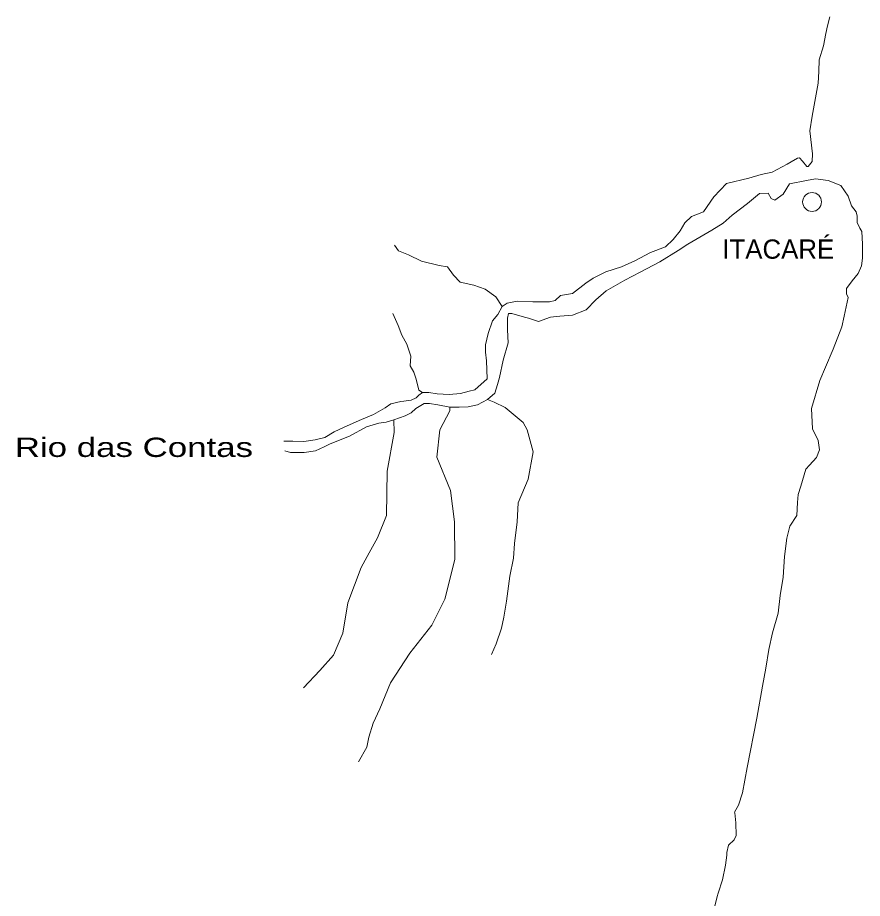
# Model space of a CAD drawing. Extents: x 47169 to 972804, y 7447977 to 9608469.
# Drawn here: x 473189 to 502148, y 8397660 to 8427856 of the extents above; entities that cross this region are included whole.
import ezdxf

# ---------------------------------------------------------------- set-up
doc = ezdxf.new("R2010")
doc.units = 0
doc.header["$LTSCALE"] = 270
doc.layers.add('1', color=7, linetype='Continuous', lineweight=13)
doc.layers.add('2', color=7, linetype='Continuous', lineweight=13)
doc.layers.add('3', color=7, linetype='Continuous')

msp = doc.modelspace()

# ---------------------------------------------------------------- linework, layer by layer
at = {"layer": '1'}
for points in [[(482317.8, 8413333.4), (482619.7, 8413333.6), (482997.1, 8413322.8), (483385.3, 8413378.3), (483719.5, 8413456), (484042.9, 8413655.3), (484387.8, 8413810.3), (484980.7, 8414076.1), (485390.4, 8414253.3), (485789.3, 8414474.8), (485983.3, 8414618.7), (486328.3, 8414696.3), (486425.4, 8414707.4), (486684.2, 8414740.7), (486856.6, 8414818.2), (486942.9, 8414906.8), (487072.2, 8415006.3), (487136.9, 8415006.4), (487287.9, 8415006.5), (487568.3, 8414962.4), (487978.1, 8414940.4), (488366.3, 8414973.8), (488668.2, 8415051.4), (488862.3, 8415095.7), (489282.7, 8415471.9), (489260.8, 8416091.3), (489228.3, 8416389.9), (489228.2, 8416633.2), (489314.4, 8417031.4), (489465.2, 8417462.8), (489648.4, 8417673), (489799.3, 8417949.6), (489971.8, 8418071.3), (490316.9, 8418137.8), (490845.4, 8418115.9), (491190.5, 8418116), (491417, 8418116.1), (491611.1, 8418160.4), (491794.4, 8418326.3), (492215, 8418392.8), (492667.8, 8418746.9), (492915.8, 8418923.9), (493358, 8419145.2), (493886.4, 8419311.3), (494350.2, 8419521.5), (494889.4, 8419798.1), (495396.3, 8419997.3), (495665.9, 8420251.7), (495903.1, 8420550.4), (496064.9, 8420815.9), (496291.3, 8421037.1), (496701.2, 8421192), (497057.1, 8421711.9), (497488.5, 8422165.4), (498254.3, 8422353.4), (498675, 8422475.1), (499052.5, 8422552.6), (499570.3, 8422829.1), (499710.5, 8422906.5), (499926.3, 8423039.2), (499991, 8423050.3), (500098.9, 8422939.7), (500239.1, 8422751.7), (500293, 8422751.7), (500422.5, 8422917.6), (500433.3, 8423183), (500347, 8423979.3), (500422.5, 8424477), (500498, 8424853), (500627.5, 8425605.1), (500659.9, 8426014.3), (500670.7, 8426412.5), (500811, 8426888.1), (500897.3, 8427308.3), (500951.2, 8427573.8), (501026.8, 8427883.4)], [(498040.3, 8401284.1), (498201.9, 8402146.8), (498525.1, 8403839), (498729.8, 8404934), (498837.6, 8405553.3), (498945.4, 8406194.8), (499063.9, 8406758.9), (499258, 8407433.6), (499333.4, 8408041.9), (499430.4, 8408672.3), (499473.5, 8409380.2), (499559.8, 8410010.6), (499656.8, 8410419.8), (499904.8, 8410784.8), (499926.3, 8411227.2), (499947.9, 8411503.7), (500034.1, 8411791.2), (500206.7, 8412377.4), (500336, 8412510.1), (500573.3, 8412775.6), (500681.1, 8413041), (500638, 8413361.8), (500433.1, 8413759.9), (500400.8, 8414456.7), (500692, 8415418.9), (500886.1, 8415872.4), (501144.9, 8416491.7), (501446.9, 8417254.8), (501522.4, 8417619.8), (501662.7, 8418261.3), (501608.8, 8418382.9), (501608.8, 8418570.9), (501802.9, 8418836.4), (502007.9, 8419079.7), (502115.7, 8419345.1), (502148.1, 8419610.6), (502148.2, 8419842.8), (502148.2, 8420086.1), (502126.6, 8420528.5), (502061.9, 8420639.1), (501964.9, 8420827.2), (501964.9, 8421048.4), (501932.5, 8421192.1), (501770.8, 8421402.3), (501662.9, 8421734.1), (501414.8, 8422099.1), (500972.6, 8422276.1), (500541.1, 8422331.4), (500228.3, 8422276.1), (499645.8, 8422154.4), (499430.1, 8421800.5), (499149.7, 8421601.4), (499020.2, 8421656.7), (498923.1, 8421833.7), (498621.1, 8421822.6), (498211.2, 8421479.7), (497682.8, 8421081.5), (497370, 8420805), (496992.5, 8420572.7), (496162, 8420085.9), (495838.5, 8419875.7), (495202.2, 8419488.5), (494533.6, 8419134.5), (494005.2, 8418857.8), (493368.9, 8418492.7), (493013.1, 8418182.9), (492678.9, 8417840), (492215.2, 8417651.8), (491773, 8417618.5), (491460.3, 8417585.2), (491039.7, 8417441.3), (490834.8, 8417507.6), (490705.4, 8417551.8), (490565.1, 8417584.9), (490133.7, 8417717.4), (490015.1, 8417706.3), (489982.8, 8417551.5), (489982.9, 8417153.3), (490004.7, 8416710.9), (489832.4, 8416113.6), (489703.2, 8415516.3), (489638.6, 8415273), (489552.5, 8414985.4), (489293.8, 8414764.1), (488948.8, 8414575.9), (488636.1, 8414509.4), (488323.4, 8414498.2), (487999.9, 8414498.1), (487590, 8414586.3), (487309.7, 8414630.4), (487223.4, 8414630.4), (487126.3, 8414630.3), (486835.3, 8414453.2), (486684.4, 8414309.4), (486479.6, 8414198.7), (486091.4, 8414065.7), (485821.9, 8413988.1), (485573.9, 8413954.8), (485153.4, 8413821.9), (484560.5, 8413500.8), (483903, 8413246)], [(489799.3, 8417949.6), (489583.4, 8418281.3), (489216.6, 8418546.6), (488828.3, 8418679.1), (488364.5, 8418789.5), (488127.1, 8419021.6), (487922, 8419309.1), (487641.6, 8419353.2), (487037.5, 8419507.8), (486584.4, 8419717.6), (486250, 8419861.2), (486109.7, 8420060.2)], [(487072.2, 8415006.3), (486942.8, 8415083.7), (486856.3, 8415459.7), (486769.9, 8415703), (486640.4, 8415913), (486672.6, 8416244.8), (486532.1, 8416665.1), (486359.4, 8416963.6), (486229.8, 8417295.3), (486046.3, 8417715.5)], [(487999.9, 8414498.1), (487999.9, 8414376.4), (487666, 8413723.7), (487558.6, 8412783.5), (488022.8, 8411644.6), (488163.5, 8410571.8), (488174.9, 8409277.8), (487830.5, 8407917.2), (487389, 8407032.2), (486634.9, 8406069.6), (485967.1, 8405051.7), (485601.1, 8404155.6), (485375.1, 8403668.8), (485224.5, 8403182.1), (485160, 8402839.2), (484880.1, 8402341.3)], [(489293.8, 8414764.1), (489520.2, 8414675.7), (489897.7, 8414487.8), (490523.4, 8413979.3), (490652.9, 8413725), (490858, 8412973), (490696.6, 8412032.8), (490351.9, 8411225.3), (490309, 8410572.8), (490223.1, 8409831.7), (490190.9, 8409322.9), (490061.8, 8408703.5), (489943.6, 8407851.8), (489857.5, 8407298.8), (489771.5, 8406922.7), (489599.2, 8406391.8), (489437.7, 8406015.7)], [(486091.4, 8414065.7), (486091.7, 8413634.4), (485855.2, 8412307), (485834.5, 8410791.8), (485522.3, 8410017.4), (485242.2, 8409508.5), (484962.2, 8408999.6), (484510.2, 8407793.7), (484338.4, 8406754), (484015.5, 8406001.7), (483552.3, 8405470.5), (482992.1, 8404872.9)], [(483903, 8413246), (483698.2, 8413146.3), (483396.3, 8413002.3), (483008.2, 8412946.8), (482544.5, 8412946.4), (482350.4, 8413001.6)], [(497049.2, 8397213.9), (497167.7, 8397722.7), (497200, 8397833.3), (497350.8, 8398297.8), (497458.5, 8398795.5), (497501.6, 8399138.4), (497501.6, 8399237.9), (497555.4, 8399481.3), (497749.4, 8399669.3), (497824.8, 8399813.1), (497814, 8400255.5), (497781.7, 8400476.7), (497770.9, 8400598.4), (497760.1, 8400620.5), (497900.2, 8400852.8), (498040.3, 8401284.1)]]:
    msp.add_lwpolyline(points, dxfattribs=at)
at = {"layer": '2'}
msp.add_circle((500422.5, 8421535.1), 323.8, dxfattribs=at)

# ---------------------------------------------------------------- texts
at = {"layer": '3'}
msp.add_text('ITACARÉ', height=662, dxfattribs=at).set_placement((497346.7, 8419588.6))
at = {"layer": '3', "width": 1.35}
msp.add_text('Rio das Contas', height=661.8, dxfattribs=at).set_placement((473090.7, 8412794))

doc.saveas('drawing.dxf')
